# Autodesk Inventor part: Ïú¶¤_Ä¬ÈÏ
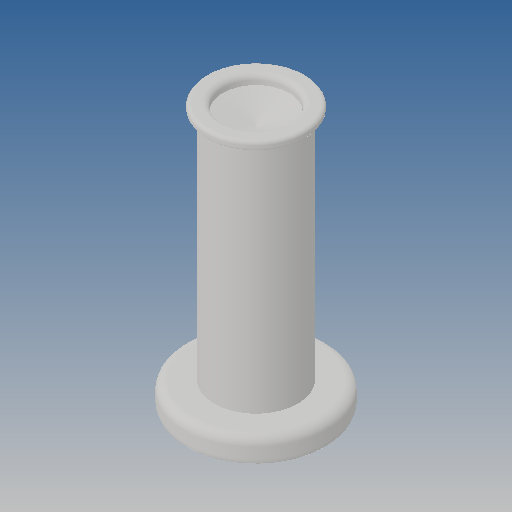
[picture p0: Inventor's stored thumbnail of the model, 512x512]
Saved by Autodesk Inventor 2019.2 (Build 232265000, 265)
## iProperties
Created: 2012-09
Part Number: Ïú¶¤_Ä¬ÈÏ
Material: Ogólny
Document SubType Name: Modeling
Designer: CADENGINEERING4
Density: 1 g/cm^3
Appearance: Domyślna
Author: CADENGINEERING4
Revision Number: ÈÎºÎ
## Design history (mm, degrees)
feature "NONE"
node "Bryła1"
